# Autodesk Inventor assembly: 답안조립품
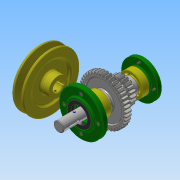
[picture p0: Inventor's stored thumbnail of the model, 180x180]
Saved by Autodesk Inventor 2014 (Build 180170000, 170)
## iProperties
Created: 2016-10
Part Number: 답안조립품
Document SubType Name: Assembly
Designer: user
Author: user
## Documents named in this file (12)
- C:\Users\user\Desktop\461008V1023\답안조립품.iam
- C:\Users\user\Desktop\461008V1023\1-본체.ipt
- C:\Users\user\Desktop\461008V1023\뒤커버.ipt
- C:\Users\user\Desktop\461008V1023\앞커버.ipt
- C:\Users\user\Desktop\461008V1023\베어링 6203.ipt
- C:\Users\user\Desktop\461008V1023\볼트 M3 x 8.ipt
- C:\Users\user\Desktop\461008V1023\볼트 M3 x 10.ipt
- C:\Users\user\Desktop\461008V1023\오일씰 28 40 8.ipt
- C:\Users\user\Desktop\461008V1023\축.ipt
- C:\Users\user\Desktop\461008V1023\키 - 6 x 6 x 22.ipt
- C:\Users\user\Desktop\461008V1023\스퍼기어.ipt
- C:\Users\user\Desktop\461008V1023\V-벨트풀리.ipt
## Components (10 placed, 4 different names)
1. 1-본체:1 — Mate:1, Mate:2, Mate:3, Mate:4, Mate:5, Mate:6
2. V-벨트풀리:1
3. ISO 4762 M3 x 8:1 — Mate:11, Mate:12
4. ISO 4762 M3 x 8:2
5. ISO 4762 M3 x 8:3
6. ISO 4762 M3 x 8:4
7. ISO 4762 M3 x 10:1 — Mate:13, Mate:14
8. ISO 4762 M3 x 10:2
9. ISO 4762 M3 x 10:3
10. ISO 4762 M3 x 10:4
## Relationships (10: Mate 10)
- Mate:1: 1-본체:1
- Mate:2: 1-본체:1
- Mate:3: 1-본체:1
- Mate:4: 1-본체:1
- Mate:5: 1-본체:1
- Mate:6: 1-본체:1
- Mate:11: ISO 4762 M3 x 8:1
- Mate:12: ISO 4762 M3 x 8:1
- Mate:13: ISO 4762 M3 x 10:1
- Mate:14: ISO 4762 M3 x 10:1
